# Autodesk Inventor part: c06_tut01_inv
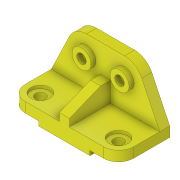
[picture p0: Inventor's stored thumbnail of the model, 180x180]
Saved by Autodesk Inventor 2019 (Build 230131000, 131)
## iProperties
Created: 2015-03
Part Number: c06_tut01_inv
Material: Generic
Document SubType Name: Modeling
Designer: Sandeep
Density: 1 g/cm^3
Appearance: Yellow
Author: Sandeep
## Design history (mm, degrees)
sketch "Sketch1"
  geometry: L1 (51, 0)-(51, 9); L2 (51, 9)-(108, 9); L3 (108, 9)-(108, 29); L4 (108, 29)-(-108, 29); L5 (-108, 29)-(-108, 9); L6 (-108, 9)-(-51, 9); L7 (-51, 9)-(-51, 0); L8 (-51, 0)-(51, 0); L9 (0, 96.725)-(0, -45.323); 1 further point
  constraints: 18 end point, 6 perpendicular, 3 point on line, 2 vertical, 1 midpoint, 2 other
  dimensions: "d1" = 20 distance of L2.end L3.end; "d2" = 57 distance between parallel lines of L5 L7; "d3" = 102 distance between parallel lines of L7 L1; "d66" = 9 distance between parallel lines of L2 L8
extrude "Extrusion1" new body sketch "Sketch1" distance "d4" = 102; taper "d5" = 0 deg
sketch "Sketch2"
  geometry: L1 (-108, -29)-(108, -29) reference; L2 (108, -29)-(72.256, -103.447); L3 (38, -125)-(-38, -125); L4 (-72.256, -103.447)-(-108, -29); L5 (0, -125)-(0, -29); L6 (51, 0)-(-51, 0) reference; A1 r 38 centre (38, -87) between (38, -125) and (72.256, -103.447); A2 r 38 centre (-38, -87) between (-72.256, -103.447) and (-38, -125); 2 further points
  constraints: 8 end point, 4 point on circle, 4 tangent, 3 midpoint, 2 centre point, 1 parallel, 1 point on line, 1 vertical, 2 other
  dimensions: "d6" = 96 distance between parallel lines of L1 L3; "d7" = 38 radius of A2; "d8" = 76 distance of L3.start L3.end
extrude "Extrusion2" join sketch "Sketch2" distance "d9" = 20; taper "d10" = 0 deg
sketch "Sketch3"
  geometry: L1 (0, 198.489)-(0, -42.784); L2 (38, 125)-(-38, 125) reference; C1 r 19 at (-38, 87); C2 r 9.5 at (-38, 87); C3 r 9.5 at (38, 87); C4 r 19 at (38, 87); 2 further points
  constraints: 4 centre point, 2 coincident, 2 end point, 2 equal radius, 1 midpoint, 1 point on line, 1 vertical, 2 other
  dimensions: "d11" = 38 diameter of C1; "d12" = 19 diameter of C2; "d13" = 76 distance of C3.centre C1.centre; "d14" = 38 distance from line of C1.centre L2
extrude "Extrusion3" join sketch "Sketch3" distance "d15" = 10; taper "d16" = 0 deg
fillet "Fillet1" dims "d17" = 30
hole "Hole3" diameter "d38" = 20; stored, may be unused: countersink angle "d42" = 90 deg, drill point angle "d44" = 118 deg; dims "d39" = 6, "d40" = 38, "d41" = 6, "d43" = 8, "d64" = 10, "d65" = 10
hole "Hole4" diameter "d47" = 20; stored, may be unused: countersink angle "d51" = 90 deg, drill point angle "d53" = 118 deg; dims "d45" = 10, "d46" = 10, "d48" = 6, "d49" = 38, "d50" = 6, "d52" = 8
workplane "Work Plane1"
sketch "Sketch4"
  geometry: L1 (-40, 0.112)-(-40, -20); L2 (-40, -20)-(-15, -82); L3 (20, -82)-(0, -82) reference; L4 (-15, -82)-(0, -82); L5 (0, -52)-(0, 0) reference; L6 (-96, 0)-(-74.447, 0) reference; 1 further point
  constraints: 6 end point, 1 collinear, 1 vertical
  dimensions: "d55" = 40 distance between parallel lines of L1 L5; "d56" = 20 distance from line of L6 L1.end; "d57" = 15 distance of L2.end L3.end
feature "Rib1" sketch "Sketch4" dims "d58" = 1, "d59" = 20, "d60" = 0, "d61" = 0, "d62" = 1, "d63" = 1
body "Solid1"
other parameters: "d54" = -108
